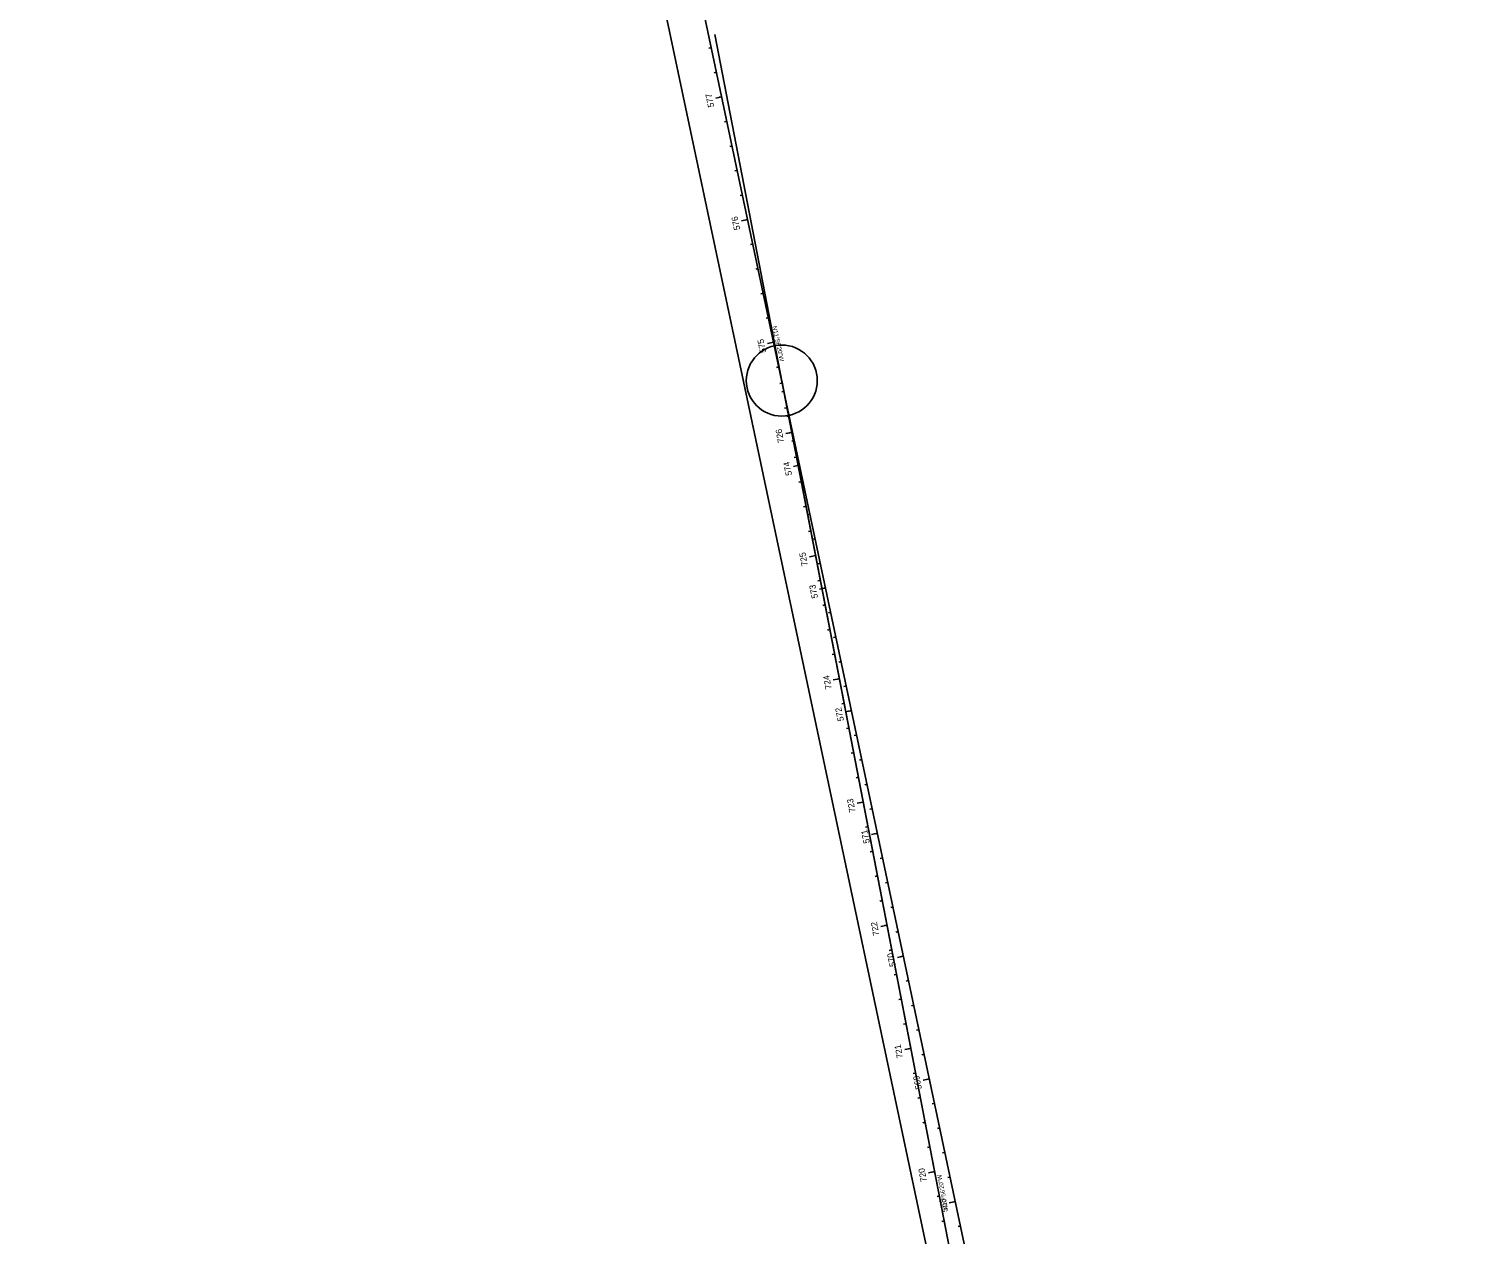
# Model space of a CAD drawing. Extents: x 2003883 to 2007688, y 399149 to 412300.
# Drawn here: x 2005065 to 2006224, y 404136 to 405097 of the extents above; entities that cross this region are included whole.
import ezdxf

# ---------------------------------------------------------------- set-up
doc = ezdxf.new("R2010")
doc.units = 0
for name, color, linetype in [('BaselineSurvey', 7, 'Continuous'), ('BaselineTextWt0', 7, 'Continuous'), ('DataBoxWt2', 7, 'Continuous'), ('Default', 7, 'Continuous'), ('EaseLine_ep', 7, 'Continuous'), ('PropertyLine_ep', 7, 'Continuous'), ('PropertyLineHook_ep', 7, 'Continuous'), ('PropertyLineSymbol_ep', 7, 'Continuous'), ('RWLine', 7, 'Continuous'), ('SubDivLine', 7, 'Continuous'), ('SubDivLineText', 7, 'Continuous'), ('SubLotNumberText', 7, 'Continuous'), ('SubVacOrigLotStaTie', 7, 'Continuous')]:
    doc.layers.add(name, color=color, linetype=linetype)

msp = doc.modelspace()

# ---------------------------------------------------------------- linework, layer by layer
at = {"layer": 'DataBoxWt2'}
for p, q in [((2005638, 404945.7), (2005636, 404945.2)), ((2005673.1, 404776), (2005671.1, 404775.6)), ((2005679.3, 404750), (2005677.4, 404749.6)), ((2005711, 404579.6), (2005709.1, 404579.2)), ((2005720.7, 404554.3), (2005718.8, 404553.9)), ((2005749, 404383.2), (2005747, 404382.9)), ((2005762.1, 404358.6), (2005757.2, 404357.6)), ((2005786.9, 404186.9), (2005782, 404185.9)), ((2005803.5, 404163), (2005801.5, 404162.5))]:
    msp.add_line(p, q, dxfattribs=at)
at = {"layer": 'Default'}
msp.add_line((2006223.9, 402174.4), (2005094.5, 407516), dxfattribs=at)
at = {"layer": 'EaseLine_ep'}
for p, q in [((2006194.6, 402168.2), (2005065.1, 407509.8)), ((2005991.3, 403129.4), (2005611.8, 405093.1))]:
    msp.add_line(p, q, dxfattribs=at)
at = {"layer": 'PropertyLine_ep'}
msp.add_line((2006223.9, 402174.4), (2005094.5, 407516), dxfattribs=at)
at = {"layer": 'PropertyLineHook_ep'}
for p, q in [((2005609, 405082.6), (2005607, 405082.2)), ((2005613.1, 405063.1), (2005611.2, 405062.6)), ((2005617.3, 405043.5), (2005612.4, 405042.5)), ((2005621.4, 405023.9), (2005619.5, 405023.5)), ((2005625.6, 405004.4), (2005623.6, 405003.9)), ((2005629.7, 404984.8), (2005627.7, 404984.4)), ((2005633.8, 404965.2), (2005631.9, 404964.8)), ((2005638, 404945.7), (2005633.1, 404944.6)), ((2005642.1, 404926.1), (2005640.1, 404925.7)), ((2005646.2, 404906.5), (2005644.3, 404906.1)), ((2005650.4, 404887), (2005648.4, 404886.5)), ((2005654.5, 404867.4), (2005652.6, 404867)), ((2005658.7, 404847.8), (2005653.8, 404846.8)), ((2005662.8, 404828.3), (2005660.8, 404827.8)), ((2005665.5, 404815.2), (2005663.5, 404814.9)), ((2005666.9, 404808.7), (2005665, 404808.3)), ((2005669.3, 404795.6), (2005667.3, 404795.2)), ((2005671.1, 404789.1), (2005669.1, 404788.7)), ((2005673.1, 404776), (2005668.2, 404775)), ((2005675.2, 404769.6), (2005673.2, 404769.1)), ((2005676.9, 404756.3), (2005674.9, 404756)), ((2005679.3, 404750), (2005674.4, 404748.9)), ((2005680.7, 404736.7), (2005678.7, 404736.3)), ((2005683.5, 404730.4), (2005681.5, 404730)), ((2005684.5, 404717.1), (2005682.5, 404716.7)), ((2005687.6, 404710.8), (2005685.7, 404710.4)), ((2005688.3, 404697.4), (2005686.3, 404697)), ((2005691.7, 404691.3), (2005689.8, 404690.9)), ((2005692.1, 404677.8), (2005687.2, 404676.8)), ((2005695.9, 404671.7), (2005693.9, 404671.3)), ((2005695.9, 404658.2), (2005693.9, 404657.8)), ((2005700, 404652.1), (2005695.1, 404651.1)), ((2005699.7, 404638.5), (2005697.7, 404638.1)), ((2005704.2, 404632.6), (2005702.2, 404632.2)), ((2005703.5, 404618.9), (2005701.5, 404618.5)), ((2005708.3, 404613), (2005706.3, 404612.6)), ((2005707.2, 404599.2), (2005705.3, 404598.9)), ((2005712.4, 404593.4), (2005710.5, 404593)), ((2005711, 404579.6), (2005706.1, 404578.7)), ((2005716.6, 404573.9), (2005714.6, 404573.5)), ((2005714.8, 404560), (2005712.9, 404559.6)), ((2005720.7, 404554.3), (2005715.8, 404553.3)), ((2005718.6, 404540.3), (2005716.7, 404540)), ((2005724.8, 404534.7), (2005722.9, 404534.3)), ((2005722.4, 404520.7), (2005720.5, 404520.3)), ((2005729, 404515.2), (2005727, 404514.8)), ((2005726.2, 404501.1), (2005724.3, 404500.7)), ((2005733.1, 404495.6), (2005731.2, 404495.2)), ((2005730, 404481.4), (2005725.1, 404480.5)), ((2005737.3, 404476), (2005735.3, 404475.6)), ((2005733.8, 404461.8), (2005731.9, 404461.4)), ((2005741.4, 404456.5), (2005736.5, 404455.4)), ((2005737.6, 404442.2), (2005735.6, 404441.8)), ((2005745.5, 404436.9), (2005743.6, 404436.5)), ((2005741.4, 404422.5), (2005739.4, 404422.1)), ((2005749.7, 404417.3), (2005747.7, 404416.9)), ((2005745.2, 404402.9), (2005743.2, 404402.5)), ((2005753.8, 404397.8), (2005751.9, 404397.4)), ((2005749, 404383.2), (2005744.1, 404382.3)), ((2005757.9, 404378.2), (2005756, 404377.8)), ((2005752.8, 404363.6), (2005750.8, 404363.2)), ((2005762.1, 404358.6), (2005757.2, 404357.6)), ((2005756.6, 404344), (2005754.6, 404343.6)), ((2005766.2, 404339.1), (2005764.3, 404338.7)), ((2005760.4, 404324.3), (2005758.4, 404324)), ((2005770.4, 404319.5), (2005768.4, 404319.1)), ((2005764.2, 404304.7), (2005762.2, 404304.3)), ((2005774.5, 404299.9), (2005772.5, 404299.5)), ((2005768, 404285.1), (2005763.1, 404284.1)), ((2005778.6, 404280.4), (2005776.7, 404280)), ((2005771.8, 404265.4), (2005769.8, 404265)), ((2005782.8, 404260.8), (2005777.9, 404259.8)), ((2005775.6, 404245.8), (2005773.6, 404245.4)), ((2005786.9, 404241.2), (2005785, 404240.8)), ((2005779.4, 404226.2), (2005777.4, 404225.8)), ((2005791, 404221.7), (2005789.1, 404221.3)), ((2005783.2, 404206.5), (2005781.2, 404206.1)), ((2005795.2, 404202.1), (2005793.2, 404201.7)), ((2005786.9, 404186.9), (2005782, 404185.9)), ((2005799.3, 404182.5), (2005797.4, 404182.1)), ((2005790.7, 404167.2), (2005788.8, 404166.9)), ((2005803.5, 404163), (2005798.6, 404161.9)), ((2005794.5, 404147.6), (2005792.6, 404147.2)), ((2005807.6, 404143.4), (2005805.6, 404143))]:
    msp.add_line(p, q, dxfattribs=at)
at = {"layer": 'RWLine'}
msp.add_circle((2005665.1, 404817.3), 28.3, dxfattribs=at)
at = {"layer": 'SubDivLine'}
msp.add_line((2005915, 403524.1), (2005665.1, 404817.3), dxfattribs=at)
at = {"layer": 'SubDivLineText'}
for p, q in [((2005617.3, 405043.5), (2005615.3, 405043.1)), ((2005638, 404945.7), (2005636, 404945.2)), ((2005658.7, 404847.8), (2005653.8, 404846.8)), ((2005673.1, 404776), (2005671.1, 404775.6)), ((2005679.3, 404750), (2005677.4, 404749.6)), ((2005692.1, 404677.8), (2005687.2, 404676.8)), ((2005700, 404652.1), (2005698.1, 404651.7)), ((2005711, 404579.6), (2005709.1, 404579.2)), ((2005720.7, 404554.3), (2005718.8, 404553.9)), ((2005730, 404481.4), (2005728.1, 404481)), ((2005741.4, 404456.5), (2005739.4, 404456.1)), ((2005749, 404383.2), (2005747, 404382.9)), ((2005762.1, 404358.6), (2005757.2, 404357.6)), ((2005768, 404285.1), (2005766, 404284.7)), ((2005782.8, 404260.8), (2005780.8, 404260.4)), ((2005786.9, 404186.9), (2005782, 404185.9)), ((2005803.5, 404163), (2005801.5, 404162.5))]:
    msp.add_line(p, q, dxfattribs=at)
at = {"layer": 'SubVacOrigLotStaTie'}
for p, q in [((2005762.1, 404358.6), (2005760.1, 404358.2)), ((2005786.9, 404186.9), (2005785, 404186.5))]:
    msp.add_line(p, q, dxfattribs=at)

# ---------------------------------------------------------------- texts
at = {"layer": 'BaselineSurvey'}
for s, rotation, p in [('570', 101.9388, (2005756.1, 404350.7)), ('720', 100.9389, (2005780.8, 404179.1))]:
    msp.add_text(s, height=4.98, rotation=rotation, dxfattribs=at).set_placement(p)
at = {"layer": 'BaselineTextWt0'}
for s, rotation, p in [('N11°56\'20"W', 281.9388, (2005657.6, 404860.4)), ('N10°56\'20"W', 100.9389, (2005797.7, 404156.7))]:
    msp.add_text(s, height=3.48, rotation=rotation, dxfattribs=at).set_placement(p)
at = {"layer": 'PropertyLineSymbol_ep'}
for s, rotation, p in [('577', 101.9388, (2005611.3, 405035.6)), ('576', 101.9388, (2005632, 404937.7)), ('575', 101.9388, (2005652.7, 404839.9)), ('726', 100.9389, (2005667, 404768.2)), ('574', 101.9388, (2005673.3, 404742.1)), ('725', 100.9389, (2005685.9, 404669.9)), ('573', 101.9388, (2005694, 404644.2)), ('724', 100.9389, (2005704.9, 404571.8)), ('572', 101.9388, (2005714.7, 404546.3)), ('723', 100.9389, (2005723.9, 404473.6)), ('571', 101.9388, (2005735.3, 404448.9)), ('722', 100.9389, (2005742.9, 404375.4)), ('570', 101.9388, (2005756.1, 404350.7)), ('721', 100.9389, (2005761.8, 404277.6)), ('569', 101.9388, (2005776.8, 404252.9)), ('720', 100.9389, (2005780.8, 404179.1)), ('568', 101.9388, (2005797.5, 404155))]:
    msp.add_text(s, height=4.98, rotation=rotation, dxfattribs=at).set_placement(p)
at = {"layer": 'SubLotNumberText'}
for s, rotation, p in [('575', 101.9388, (2005652.7, 404839.9)), ('725', 100.9389, (2005685.9, 404669.9)), ('570', 101.9388, (2005756.1, 404350.7)), ('720', 100.9389, (2005780.8, 404179.1))]:
    msp.add_text(s, height=4.98, rotation=rotation, dxfattribs=at).set_placement(p)

doc.saveas('drawing.dxf')
